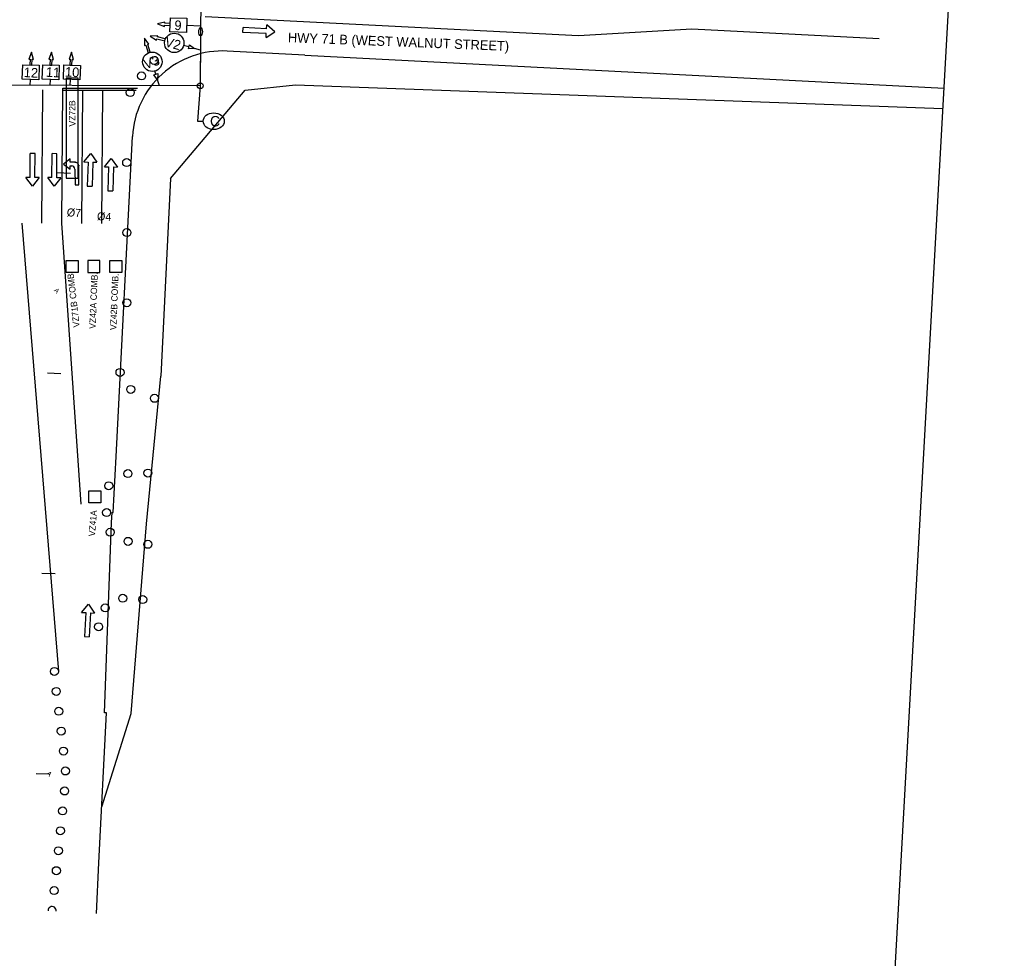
# Model space of a CAD drawing. Extents: x 0 to 1361828, y 0 to 1470398.
# Drawn here: x 680949.1 to 681440.9, y 734647.2 to 735115.8 of the extents above; entities that cross this region are included whole.
import ezdxf

# ---------------------------------------------------------------- set-up
doc = ezdxf.new("R2010")
doc.units = 0
for name, color, linetype in [('$', 7, 'Continuous'), ('090338 Base_Design base 1-1 - R_Horz Alg', 7, 'Continuous'), ('border All Plan 20-40_Border 1 - Level 1', 7, 'Continuous'), ('MOT Stage 1', 7, 'Continuous'), ('MOT Stage 1 Lanes', 7, 'Continuous'), ('R_Horz Alg Station', 7, 'Continuous'), ('RW-EX', 7, 'Continuous'), ('RW-PR', 7, 'Continuous'), ('SIGNAL-PLAN VIEW LABLES', 7, 'Continuous'), ('TITEXT', 7, 'Continuous'), ('Video-Zones-pr', 7, 'Continuous')]:
    doc.layers.add(name, color=color, linetype=linetype)

# ---------------------------------------------------------------- blocks, each defined once
blk = doc.blocks.new('BAREL_1514')
at = {"layer": 'MOT Stage 1'}
blk.add_circle((-0.01, 0), 2, dxfattribs=at)
blk = doc.blocks.new('BAREL_1515')
at = {"layer": 'MOT Stage 1'}
blk.add_circle((-0.01, 0), 2, dxfattribs=at)
blk = doc.blocks.new('BAREL_1516')
at = {"layer": 'MOT Stage 1'}
blk.add_circle((-0.01, 0), 2, dxfattribs=at)
blk = doc.blocks.new('BAREL_1517')
at = {"layer": 'MOT Stage 1'}
blk.add_circle((-0.01, 0), 2, dxfattribs=at)
blk = doc.blocks.new('BAREL_1518')
at = {"layer": 'MOT Stage 1'}
blk.add_circle((-0.01, 0), 2, dxfattribs=at)
blk = doc.blocks.new('BAREL_1520')
at = {"layer": 'MOT Stage 1'}
blk.add_circle((0, -0.01), 2, dxfattribs=at)
blk = doc.blocks.new('BAREL_1521')
at = {"layer": 'MOT Stage 1'}
blk.add_circle((0, -0.01), 2, dxfattribs=at)
blk = doc.blocks.new('BAREL_1522')
at = {"layer": 'MOT Stage 1'}
blk.add_circle((0, -0.01), 2, dxfattribs=at)
blk = doc.blocks.new('BAREL_1523')
at = {"layer": 'MOT Stage 1'}
blk.add_circle((0, -0.01), 2, dxfattribs=at)
blk = doc.blocks.new('SARROW_172')
at = {"layer": 'MOT Stage 1'}
for p, q in [((0, 0), (-6, 0)), ((0, -29.4), (0, 0)), ((-6, -29.4), (-6, 0)), ((-6, -29.4), (-11, -29.4)), ((-3, -39.8), (-11, -29.4)), ((5, -29.4), (-3, -39.8)), ((5, -29.4), (0, -29.4))]:
    blk.add_line(p, q, dxfattribs=at)
blk = doc.blocks.new('SARROW_176')
at = {"layer": 'MOT Stage 1'}
for p, q in [((-6, -29.4), (-6, 0)), ((0, 0), (-6, 0)), ((0, -29.4), (0, 0)), ((-6, -29.4), (-11, -29.4)), ((-3, -39.8), (-11, -29.4)), ((5, -29.4), (-3, -39.8)), ((5, -29.4), (0, -29.4))]:
    blk.add_line(p, q, dxfattribs=at)
blk = doc.blocks.new('SARROW_177')
at = {"layer": 'MOT Stage 1'}
for p, q in [((0, 0), (-6, 0)), ((0, -29.4), (0, 0)), ((-6, -29.4), (-6, 0)), ((-6, -29.4), (-11, -29.4)), ((-3, -39.8), (-11, -29.4)), ((5, -29.4), (-3, -39.8)), ((5, -29.4), (0, -29.4))]:
    blk.add_line(p, q, dxfattribs=at)
blk = doc.blocks.new('SARROW_182')
at = {"layer": 'MOT Stage 1'}
for p, q in [((0, 0), (-6, 0)), ((0, -29.4), (0, 0)), ((-6, -29.4), (-6, 0)), ((-6, -29.4), (-11, -29.4)), ((-3, -39.8), (-11, -29.4)), ((5, -29.4), (-3, -39.8)), ((5, -29.4), (0, -29.4))]:
    blk.add_line(p, q, dxfattribs=at)
blk = doc.blocks.new('BAREL_1564')
at = {"layer": 'MOT Stage 1'}
blk.add_circle((0, -0.01), 2, dxfattribs=at)
blk = doc.blocks.new('BAREL_1565')
at = {"layer": 'MOT Stage 1'}
blk.add_circle((0, -0.01), 2, dxfattribs=at)
blk = doc.blocks.new('BAREL_1566')
at = {"layer": 'MOT Stage 1'}
blk.add_circle((0, -0.01), 2, dxfattribs=at)
blk = doc.blocks.new('BAREL_1567')
at = {"layer": 'MOT Stage 1'}
blk.add_circle((0, -0.01), 2, dxfattribs=at)
blk = doc.blocks.new('BAREL_1568')
at = {"layer": 'MOT Stage 1'}
blk.add_circle((-0.01, 0), 2, dxfattribs=at)
blk = doc.blocks.new('BAREL_1569')
at = {"layer": 'MOT Stage 1'}
blk.add_circle((-0.01, 0), 2, dxfattribs=at)
blk = doc.blocks.new('BAREL_1570')
at = {"layer": 'MOT Stage 1'}
blk.add_circle((-0.01, 0), 2, dxfattribs=at)
blk = doc.blocks.new('BAREL_1571')
at = {"layer": 'MOT Stage 1'}
blk.add_circle((-0.01, 0), 2, dxfattribs=at)
blk = doc.blocks.new('BAREL_1572')
at = {"layer": 'MOT Stage 1'}
blk.add_circle((-0.01, 0), 2, dxfattribs=at)
blk = doc.blocks.new('BAREL_1573')
at = {"layer": 'MOT Stage 1'}
blk.add_circle((-0.01, 0), 2, dxfattribs=at)
blk = doc.blocks.new('BAREL_1574')
at = {"layer": 'MOT Stage 1'}
blk.add_circle((-0.01, 0), 2, dxfattribs=at)
blk = doc.blocks.new('SARROW_185')
at = {"layer": 'MOT Stage 1'}
for p, q in [((0, 0), (-6, 0)), ((0, -29.4), (0, 0)), ((-6, -29.4), (-6, 0)), ((-6, -29.4), (-11, -29.4)), ((-3, -39.8), (-11, -29.4)), ((5, -29.4), (-3, -39.8)), ((5, -29.4), (0, -29.4))]:
    blk.add_line(p, q, dxfattribs=at)
blk = doc.blocks.new('BAREL_1583')
at = {"layer": 'MOT Stage 1'}
blk.add_circle((-0.01, 0), 2, dxfattribs=at)
blk = doc.blocks.new('BAREL_1584')
at = {"layer": 'MOT Stage 1'}
blk.add_circle((-0.01, 0), 2, dxfattribs=at)
blk = doc.blocks.new('BAREL_1585')
at = {"layer": 'MOT Stage 1'}
blk.add_circle((-0.01, 0), 2, dxfattribs=at)
blk = doc.blocks.new('BAREL_1586')
at = {"layer": 'MOT Stage 1'}
blk.add_circle((-0.01, 0), 2, dxfattribs=at)
blk = doc.blocks.new('BAREL_1587')
at = {"layer": 'MOT Stage 1'}
blk.add_circle((-0.01, 0), 2, dxfattribs=at)
blk = doc.blocks.new('BAREL_1588')
at = {"layer": 'MOT Stage 1'}
blk.add_circle((-0.01, 0), 2, dxfattribs=at)
blk = doc.blocks.new('BAREL_1589')
at = {"layer": 'MOT Stage 1'}
blk.add_circle((-0.01, 0), 2, dxfattribs=at)
blk = doc.blocks.new('BAREL_1590')
at = {"layer": 'MOT Stage 1'}
blk.add_circle((-0.01, 0), 2, dxfattribs=at)
blk = doc.blocks.new('BAREL_1591')
at = {"layer": 'MOT Stage 1'}
blk.add_circle((-0.01, 0), 2, dxfattribs=at)
blk = doc.blocks.new('BAREL_1592')
at = {"layer": 'MOT Stage 1'}
blk.add_circle((-0.01, 0), 2, dxfattribs=at)
blk = doc.blocks.new('BAREL_1593')
at = {"layer": 'MOT Stage 1'}
blk.add_circle((-0.01, 0), 2, dxfattribs=at)
blk = doc.blocks.new('BAREL_1594')
at = {"layer": 'MOT Stage 1'}
blk.add_circle((-0.01, 0), 2, dxfattribs=at)
blk = doc.blocks.new('SARROW_186')
at = {"layer": 'MOT Stage 1'}
for p, q in [((-6, -29.4), (-6, 0)), ((0, 0), (-6, 0)), ((0, -29.4), (0, 0)), ((-6, -29.4), (-11, -29.4)), ((-3, -39.8), (-11, -29.4)), ((5, -29.4), (-3, -39.8)), ((5, -29.4), (0, -29.4))]:
    blk.add_line(p, q, dxfattribs=at)

msp = doc.modelspace()

# ---------------------------------------------------------------- linework, layer by layer
at = {"layer": '$'}
msp.add_line((681039.44, 735107.83), (681039.25, 735082.83), dxfattribs=at)
msp.add_lwpolyline([(680910.95, 735083.16), (680920.66, 735202.66), (681040.12, 735198.43), (681039.25, 735082.83), (680910.95, 735083.16)], dxfattribs=at)
msp.add_circle((681039.25, 735082.83), 1.5, dxfattribs=at)
msp.add_ellipse((681039.45, 735109.85), major_axis=(-0.01, -2.02), ratio=0.447722, dxfattribs=at)
at = {"layer": 'border All Plan 20-40_Border 1 - Level 1'}
msp.add_line((681384.1, 734599.57), (681440.93, 735625.3), dxfattribs=at)
at = {"layer": 'MOT Stage 1'}
for points in [[(680976.62, 735044.72), (680976.94, 735044.72), (680974.21, 735044.7), (680974.2, 735046.29), (680970.92, 735043.73), (680974.23, 735041.21), (680974.22, 735042.8), (680975.05, 735042.81)], [(680976.65, 735041.23), (680976.7, 735033.43), (680978.61, 735033.45)], [(680978.61, 735033.45), (680978.54, 735043.15), (680978.54, 735042.83)]]:
    msp.add_lwpolyline(points, dxfattribs=at)
for centre, radius, start, end in [((680976.64, 735042.82), 1.9, 0.3996, 90.3996), ((680975.06, 735041.22), 1.59, 0.3996, 90.3996), ((680965.25, 734671.07), 2, 349.7483, 183.9093)]:
    msp.add_arc(centre, radius, start, end, dxfattribs=at)
at = {"layer": 'MOT Stage 1 Lanes'}
for p, q in [((681041.8, 735117.48), (681228.28, 735107.88)), ((681228.28, 735107.88), (681284.77, 735111.21)), ((681284.77, 735111.21), (681378.4, 735106.37)), ((680950.15, 735014.32), (680968.4, 734790.33)), ((680979.71, 734873.94), (680970.15, 735014.19))]:
    msp.add_line(p, q, dxfattribs=at)
for points in [[(680960.15, 735014.25), (680960.6, 735080.81)], [(680970.15, 735014.19), (680970.61, 735081.6), (681007.85, 735081.6)], [(680970.6, 735080.6), (681007.28, 735080.6)], [(680980.15, 735014.12), (680980.6, 735080.67)], [(680990.15, 735014.05), (680990.6, 735080.6)]]:
    msp.add_lwpolyline(points, dxfattribs=at)
at = {"layer": 'R_Horz Alg Station'}
for points in [[(680967.77, 735039.47), (680974.43, 735039.13)], [(680962.88, 734939.44), (680969.54, 734939.26)], [(680960.07, 734839.48), (680966.73, 734839.29)], [(680957.26, 734739.52), (680963.92, 734739.33)]]:
    msp.add_lwpolyline(points, dxfattribs=at)
at = {"layer": 'RW-EX'}
for p, q in [((681091.59, 735098.17), (681052.68, 735100.18)), ((681091.59, 735098.17), (681410.81, 735081.67)), ((680997.23, 734897.78), (681005.41, 735057.54)), ((680995.79, 734869.71), (680997.23, 734897.78))]:
    msp.add_line(p, q, dxfattribs=at)
msp.add_lwpolyline([(680987.37, 734669.6), (680988.64, 734694.88), (680992.39, 734769.78), (680991.5, 734769.81), (680995.01, 734864.75), (680995.19, 734869.73), (680995.79, 734869.71)], dxfattribs=at)
msp.add_arc((681050.35, 735055.24), 45, 87.0415, 177.0663, dxfattribs=at)
at = {"layer": 'RW-PR'}
for p, q in [((681061.65, 735080.69), (681086.82, 735083.39)), ((681024.36, 735036.57), (681061.65, 735080.69)), ((681024.36, 735036.57), (681019.52, 734937.85))]:
    msp.add_line(p, q, dxfattribs=at)
for points in [[(681086.82, 735083.39), (681410.25, 735071.44)], [(680990.05, 734722.92), (681004.78, 734769.38), (681012.45, 734864.05), (681019.52, 734937.85)]]:
    msp.add_lwpolyline(points, dxfattribs=at)
at = {"layer": 'SIGNAL-PLAN VIEW LABLES'}
for p, q in [((681021.56, 735114.66), (681017.97, 735113.73)), ((681017.97, 735113.73), (681021.45, 735112.44)), ((681021.45, 735112.44), (681021.48, 735113.05)), ((681021.48, 735113.05), (681024.19, 735112.91)), ((681021.53, 735114.05), (681021.56, 735114.66)), ((681024.23, 735113.91), (681021.53, 735114.05)), ((681024.19, 735112.91), (681024.23, 735113.91)), ((680954.97, 735099.63), (680953.68, 735096.15)), ((680955.89, 735096.03), (680954.97, 735099.63)), ((680964.97, 735099.6), (680963.68, 735096.13)), ((680965.89, 735096.01), (680964.97, 735099.6)), ((680975, 735099.59), (680973.71, 735096.11)), ((680975.93, 735096), (680975, 735099.59)), ((680953.68, 735096.15), (680954.28, 735096.12)), ((680954.28, 735096.12), (680954.13, 735093.23)), ((680954.13, 735093.23), (680955.14, 735093.2)), ((680955.14, 735093.2), (680955.29, 735096.06)), ((680955.29, 735096.06), (680955.89, 735096.03)), ((680963.68, 735096.13), (680964.28, 735096.09)), ((680964.28, 735096.09), (680964.13, 735093.21)), ((680964.13, 735093.21), (680965.14, 735093.17)), ((680965.14, 735093.17), (680965.29, 735096.04)), ((680965.29, 735096.04), (680965.89, 735096.01)), ((680973.71, 735096.11), (680974.32, 735096.08)), ((680974.32, 735096.08), (680974.17, 735093.2)), ((680974.17, 735093.2), (680975.18, 735093.16)), ((680975.18, 735093.16), (680975.32, 735096.03)), ((680975.32, 735096.03), (680975.93, 735096))]:
    msp.add_line(p, q, dxfattribs=at)
for points in [[(681024.23, 735113.91), (681021.53, 735114.05), (681021.56, 735114.66), (681017.97, 735113.73), (681021.45, 735112.44), (681021.48, 735113.05), (681024.19, 735112.91)], [(681039.48, 735112.6), (681032.46, 735112.95)], [(681017.87, 735107.25), (681018.02, 735107.83), (681014.32, 735107.61), (681017.48, 735105.68), (681017.63, 735106.27), (681021.54, 735105.29), (681021.78, 735106.27), (681017.87, 735107.25)], [(681021.78, 735106.27), (681017.87, 735107.25), (681018.02, 735107.83), (681014.32, 735107.61), (681017.48, 735105.68), (681017.63, 735106.27), (681021.54, 735105.29)], [(681013, 735103.4), (681013.58, 735103.58), (681011.43, 735106.61), (681011.47, 735102.9), (681012.04, 735103.09), (681013.28, 735099.25), (681014.24, 735099.56), (681013, 735103.4)], [(681014.24, 735099.56), (681013, 735103.4), (681013.58, 735103.58), (681011.43, 735106.61), (681011.47, 735102.9), (681012.04, 735103.09), (681013.28, 735099.25)], [(681033.6, 735102.25), (681030.96, 735103)], [(680955.14, 735093.2), (680955.29, 735096.06), (680955.89, 735096.03), (680954.97, 735099.63), (680953.68, 735096.15), (680954.28, 735096.12), (680954.13, 735093.23)], [(680965.14, 735093.17), (680965.29, 735096.04), (680965.89, 735096.01), (680964.97, 735099.6), (680963.68, 735096.13), (680964.28, 735096.09), (680964.13, 735093.21)], [(680975.18, 735093.16), (680975.32, 735096.03), (680975.93, 735096), (680975, 735099.59), (680973.71, 735096.11), (680974.32, 735096.08), (680974.17, 735093.2)], [(681039.39, 735100.67), (681036.45, 735101.47)], [(681017.04, 735088.58), (681016.52, 735090.14)], [(680954.32, 735083.05), (680954.44, 735086.05)], [(680964.32, 735083.02), (680964.44, 735086.02)], [(680974.34, 735083), (680974.45, 735085.99)], [(681018.93, 735082.88), (681017.97, 735085.77)], [(681039.25, 735082.83), (681037.88, 735065.18), (681040.74, 735065.18)]]:
    msp.add_lwpolyline(points, dxfattribs=at)
for points in [[(681024.08, 735109.71), (681024.33, 735116.84), (681032.58, 735116.56), (681032.33, 735109.36)], [(681036.45, 735101.47), (681033.32, 735101.25), (681033.88, 735103.25)], [(680950.31, 735086.22), (680950.56, 735093.36), (680958.82, 735093.07), (680958.57, 735085.87)], [(680960.35, 735086.2), (680960.6, 735093.33), (680968.86, 735093.05), (680968.61, 735085.85)], [(680970.91, 735086.17), (680971.16, 735093.3), (680979.41, 735093.02), (680979.16, 735085.82)], [(681017.97, 735085.77), (681016.05, 735088.26), (681018.03, 735088.9)]]:
    msp.add_lwpolyline(points, close=True, dxfattribs=at)
for centre in [(681026.27, 735104.24), (681015.33, 735094.84)]:
    msp.add_circle(centre, 4.85, dxfattribs=at)
msp.add_ellipse((681046, 735065.14), major_axis=(-5.27, 0), ratio=0.790685, dxfattribs=at)
at = {"layer": 'Video-Zones-pr'}
msp.add_lwpolyline([(680972.35, 735086.67), (680972.3, 735036.67), (680978.3, 735036.67), (680978.35, 735086.67)], close=True, dxfattribs=at)
for points in [[(680978.25, 734995.6), (680978.25, 734989.6), (680972.25, 734989.6), (680972.25, 734995.6), (680978.25, 734995.6)], [(680983.15, 734995.6), (680983.15, 734989.6), (680989.15, 734989.6), (680989.15, 734995.6), (680983.15, 734995.6)], [(681000.15, 734995.6), (681000.15, 734989.6), (680994.15, 734989.6), (680994.15, 734995.6), (681000.15, 734995.6)], [(680989.66, 734874.6), (680983.66, 734874.6), (680983.66, 734880.6), (680989.66, 734880.6), (680989.66, 734874.6)]]:
    msp.add_lwpolyline(points, dxfattribs=at)

# ---------------------------------------------------------------- block references
at = {"layer": 'MOT Stage 1'}
for name, p, xscale, yscale, rotation in [('SARROW_176', (681060.53, 735109.52), 0.40000000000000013, -0.40000000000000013, -93.21769625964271), ('SARROW_172', (680956.78, 735049.01), 0.4075873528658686, 0.4075873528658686, -0.42203112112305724), ('SARROW_177', (680967.68, 735048.94), 0.4075873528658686, 0.4075873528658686, -0.42203112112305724), ('SARROW_186', (680982.82, 735032.79), 0.4075873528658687, 0.40758735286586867, 178.17728500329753), ('SARROW_182', (680993.07, 735030.41), 0.4075873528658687, 0.40758735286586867, 178.17728500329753), ('SARROW_185', (680981.39, 734807.87), 0.4075873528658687, 0.40758735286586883, 176.95379060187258)]:
    msp.add_blockref(name, p, dxfattribs=dict(at, xscale=xscale, yscale=yscale, rotation=rotation))
for name, p in [('BAREL_1574', (681016.28, 735095.49)), ('BAREL_1573', (681009.94, 735087.76)), ('BAREL_1572', (681004.33, 735079.48)), ('BAREL_1571', (681002.52, 735044.53)), ('BAREL_1570', (681002.61, 735009.53)), ('BAREL_1569', (681002.57, 734974.53)), ('BAREL_1568', (680999.19, 734939.69)), ('BAREL_1514', (681004.53, 734931.24)), ('BAREL_1515', (681016.39, 734926.8)), ('BAREL_1517', (681003.14, 734889.23)), ('BAREL_1516', (681013.14, 734889.49)), ('BAREL_1518', (680993.55, 734883.12)), ('BAREL_1565', (680992.49, 734869.8)), ('BAREL_1564', (680994.29, 734859.96)), ('BAREL_1520', (681003.19, 734855.4)), ('BAREL_1521', (681013.07, 734853.91)), ('BAREL_1522', (681000.55, 734826.98)), ('BAREL_1523', (681010.53, 734826.35)), ('BAREL_1566', (680991.79, 734822.17)), ('BAREL_1567', (680988.5, 734812.72)), ('BAREL_1594', (680966.41, 734790.43)), ('BAREL_1593', (680967.35, 734780.48)), ('BAREL_1592', (680968.59, 734770.55)), ('BAREL_1591', (680969.8, 734760.63)), ('BAREL_1590', (680970.94, 734750.69)), ('BAREL_1589', (680971.9, 734740.74)), ('BAREL_1588', (680971.5, 734730.75)), ('BAREL_1587', (680970.49, 734720.8)), ('BAREL_1586', (680969.42, 734710.86)), ('BAREL_1585', (680968.4, 734700.91)), ('BAREL_1584', (680967.39, 734690.96)), ('BAREL_1583', (680966.27, 734681.02))]:
    msp.add_blockref(name, p, dxfattribs=at)

# ---------------------------------------------------------------- texts
at = {"layer": '$'}
for s, height, rotation, p in [('HWY 71 B (WEST WALNUT STREET)', 4.8, 357.7394, (681082.99, 735104.62)), ('VZ72B', 3.2, 90.6151, (680976.97, 735062.52)), ('VZ71B COMB.', 3.2, 96.5113, (680979.07, 734962.4)), ('VZ42A COMB.', 3.2, 87.7397, (680986.98, 734961.41)), ('VZ42B COMB.', 3.2, 87.7397, (680997.35, 734960.8)), ('VZ41A', 3.2, 85.2806, (680986.65, 734857.77))]:
    msp.add_text(s, height=height, rotation=rotation, dxfattribs=at).set_placement(p)
at = {"layer": '090338 Base_Design base 1-1 - R_Horz Alg'}
for p in [(680965.98, 734980.49), (680962.23, 734739.27)]:
    msp.add_text('A', height=2.4, rotation=315.2103, dxfattribs=at).set_placement(p)
at = {"layer": 'SIGNAL-PLAN VIEW LABLES'}
for s, rotation, p in [('9', 357.0414, (681026.25, 735110.74)), ('V2', 345.0145, (681021.21, 735102.61)), ('V3', 18.0751, (681011.99, 735091.11)), ('12', 357.0414, (680951, 735087.21)), ('11', 357.0414, (680962.07, 735087.36)), ('10', 357.0414, (680971.6, 735087.46))]:
    msp.add_text(s, height=4.8, rotation=rotation, dxfattribs=at).set_placement(p)
msp.add_text('C', height=5.2, dxfattribs=at).set_placement((681044.14, 735062.54))
at = {"layer": 'TITEXT'}
for s, p in [('%%C7', (680972.49, 735017.72)), ('%%C4', (680987.58, 735015.81))]:
    msp.add_text(s, height=4, rotation=356.2723, dxfattribs=at).set_placement(p)

doc.saveas('drawing.dxf')
